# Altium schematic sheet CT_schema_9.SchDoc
size 281 x 153 mm
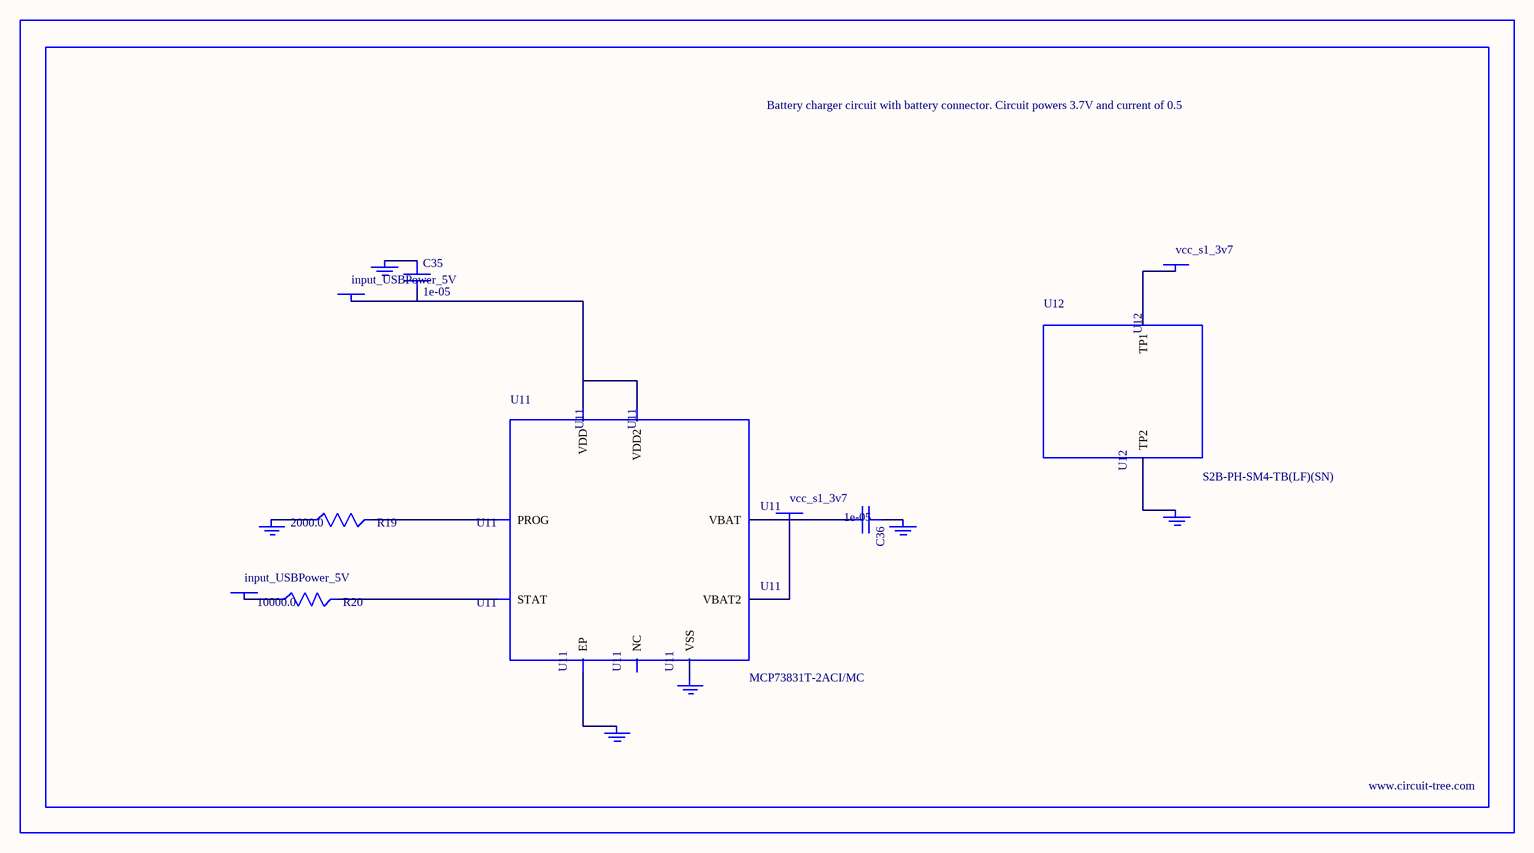
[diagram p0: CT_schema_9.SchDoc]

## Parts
BORDER8  (no value)
C35  1e-05  [C1206]
C36  1e-05  [C1206]
GND_INSTANCE_8_0  (no value)
GND_INSTANCE_8_1  (no value)
GND_INSTANCE_8_2  (no value)
GND_INSTANCE_8_3  (no value)
GND_INSTANCE_8_4  (no value)
GND_INSTANCE_8_5  (no value)
POWER_INSTANCE_8_0  input_USBPower_5V
POWER_INSTANCE_8_1  input_USBPower_5V
POWER_INSTANCE_8_2  vcc_s1_3v7
POWER_INSTANCE_8_3  vcc_s1_3v7
R19  2000.0  [R0603]
R20  10000.0  [R0603]
U11  MCP73831T-2ACI/MC  [DFN8_2X3MC]
U12  S2B-PH-SM4-TB(LF)(SN)  [JST-2-SMD]

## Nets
NetC35_1: C35.1 GND_INSTANCE_8_0.0(GND)
NetC35_2: C35.2 POWER_INSTANCE_8_0.0(PWR) U11.1(VDD) U11.2(VDD2)
NetC36_1: C36.1 GND_INSTANCE_8_1.0(GND)
NetC36_2: C36.2 POWER_INSTANCE_8_2.0(PWR) U11.3(VBAT) U11.4(VBAT2)
NetGND_INSTANCE_8_2_0: GND_INSTANCE_8_2.0(GND) R19.1
NetGND_INSTANCE_8_3_0: GND_INSTANCE_8_3.0(GND) U11.9(EP)
NetGND_INSTANCE_8_4_0: GND_INSTANCE_8_4.0(GND) U11.6(VSS)
NetGND_INSTANCE_8_5_0: GND_INSTANCE_8_5.0(GND) U12.2(TP2)
NetPOWER_INSTANCE_8_1_0: POWER_INSTANCE_8_1.0(PWR) R20.1
NetPOWER_INSTANCE_8_3_0: POWER_INSTANCE_8_3.0(PWR) U12.1(TP1)
NetR19_2: R19.2 U11.8(PROG)
NetR20_2: R20.2 U11.5(STAT)

Not connected (* = marked no-connect by the designer): U11 7(NC)

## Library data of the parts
BORDER8 = BORDER_PAGE8
C35 C36 = C1206C106K3RACTU
GND_INSTANCE_8_0-GND_INSTANCE_8_5 = GND
POWER_INSTANCE_8_0-POWER_INSTANCE_8_3 = PWR
R19 = RC0603JR-072KL
R20 = RC0603JR-0710KL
